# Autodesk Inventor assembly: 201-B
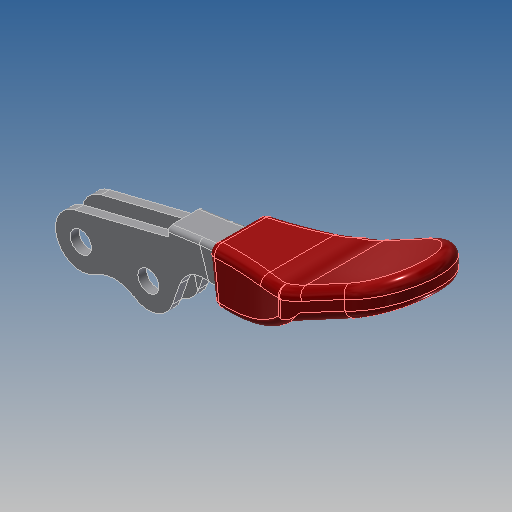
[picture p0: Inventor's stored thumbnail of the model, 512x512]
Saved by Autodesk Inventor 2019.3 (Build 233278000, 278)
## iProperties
Created: 2012-01
Part Number: 201-B
Material: Ogólny
Document SubType Name: Assembly
Designer: CADENGINEERING4
Author: CADENGINEERING4
Revision Number: ÈÎºÎ
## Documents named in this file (3)
- E:\STRONA\Horizontal toggle clamp\CH-201-B\201-B.iam
- E:\STRONA\Horizontal toggle clamp\CH-201-B\201-B-05.ipt
- E:\STRONA\Horizontal toggle clamp\CH-201-B\201-B-03.ipt
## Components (2 placed, 2 different names)
1. 201-B-05_15
2. 201-B-03_16
